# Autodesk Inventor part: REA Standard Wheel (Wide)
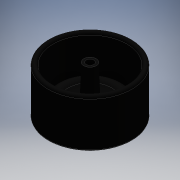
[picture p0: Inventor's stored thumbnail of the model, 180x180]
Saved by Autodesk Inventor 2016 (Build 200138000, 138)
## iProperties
Created: 2015-05
Part Number: REA Standard Wheel (Wide)
Material: Generic
Document SubType Name: Modeling
Designer: Brett
Density: 1 g/cm^3
Appearance: Black
Author: Brett
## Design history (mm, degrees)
sketch "Sketch2"
  geometry: L1 (16.5, 13.7)-(16.5, -5); L2 (11.5, -5)-(10.8, -1.029); L3 (0.1, -4.427)-(0, -4.427); L4 (16.5, 13.7)-(0, 13.7); L5 (0, -4.427)-(0, 13.7); A1 r 11 centre (14, 5.712) between (11.5, -5) and (16.5, -5); A2 r 15.413 centre (-0.015, 10.986) between (0.1, -4.427) and (9.924, -0.794); A3 r 0.5 centre (10.307, -1.116) between (10.8, -1.029) and (9.924, -0.794); 1 further point
  constraints: 10 end point, 6 point on circle, 3 centre point, 2 horizontal, 1 tangent, 1 vertical
  dimensions: "d3" = 11 radius of A1; "d5" = 170 deg angle of L2 L1; "d6" = 0.1 horizontal distance of L3.start point (0, 0); "d9" = 15.413 radius of A2; "d11" = 0.5 radius of A3; "d12" = 18.7 distance from line of L4 L1.end; "d14" = 16.5 horizontal distance of point (0, 0) L1.end; "d15" = 11.5 horizontal distance of point (0, 0) L2.start
revolve "Revolution1" sketch "Sketch2" stored, may be unused: angle "d16" = 90 deg
shell "Shell1" dims "d17" = 2
workplane "Work Plane1"
sketch "Sketch3"
  geometry: C1 r 3 at (0, 0); 1 further point
  constraints: 1 centre point, 1 coincident
  dimensions: "d19" = 6 diameter of C1
extrude "Extrusion1" join sketch "Sketch3" stored distance "d20" = 10; taper "d21" = 0 deg
feature "FaceDraft1" dims angle "d22" = 2 deg
hole "Hole1" diameter "d45" = 3; stored, may be unused: countersink angle "d49" = 90 deg, drill point angle "d51" = 0 deg; dims "d43" = 10, "d44" = 10, "d46" = 6, "d47" = 4, "d48" = 2, "d50" = 11.5
workplane "Work Plane2"
feature "OffsetSrf1" dims "d32" = 0.75, "d33" = 0.75
sketch "Sketch4"
  geometry: L1 (-0.462, 2.309)-(-2.829, 8.023); L2 (0.462, 2.309)-(2.829, 8.023); L3 (0, 2.307)-(0, 0); A1 r 9.33 centre (0, 0) between (2.323, 9.036) and (-2.323, 9.036); A2 r 0.75 centre (2.136, 8.31) between (2.829, 8.023) and (2.323, 9.036); A3 r 0.75 centre (-2.136, 8.31) between (-2.323, 9.036) and (-2.829, 8.023); A4 r 0.5 centre (0, 2.5) between (-0.462, 2.309) and (0.462, 2.309); 3 further points
  constraints: 10 point on circle, 6 end point, 6 tangent, 4 centre point, 2 point on line, 1 coincident, 1 equal radius, 1 vertical
  dimensions: "d23" = 18.66 diameter of A1; "d26" = 45 deg angle of L1 L2; "d27" = 22.5 deg angle of L3 L2; "d28" = 0.75 radius of A2; "d29" = 0.5 radius of A4; "d30" = 2.5 distance of point (0, 0) A4.centre
extrude "Extrusion2" cut sketch "Sketch4" stored distance "d34" = 3.25; taper "d35" = 0 deg
workaxis "Work Axis1"
pattern_circular "Circular Pattern1" dims angle "d37" = 360 deg
feature "FaceDraft3" dims angle "d52" = 2.5 deg
fillet "Fillet1" dims "d53" = 0.45, "d54" = 0.5, "d55" = 1
body "Solid1"
body "Srf2"
other parameters: "d18" = 0, "d31" = -4.5
